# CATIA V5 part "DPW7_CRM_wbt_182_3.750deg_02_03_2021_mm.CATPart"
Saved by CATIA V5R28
Part number: DPW7_CRM_wbt_182_3.750deg_02_03_2021
Bounding box of the stored display mesh (mm): x 2349.5 to 66711.891, y 0 to 29464.422, z 2310.119 to 8715.756
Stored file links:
  Z:\Scratch\04_CAD_Allgemein\Flight2Jig\Output\DPW-7\CATPart\DPW7_CRM_wbt_182_3.750deg_02_03_2021.CATPart
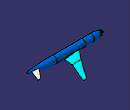
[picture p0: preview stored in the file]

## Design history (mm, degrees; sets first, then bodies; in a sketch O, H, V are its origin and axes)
Set1
  DatumSurface1 "Clean_Wing"
  DatumSurface2 "Fuselage"
  DatumSurface3 "HTP"
  DatumSurface4 "Symmetry"
  DatumSurface5 "Farfield"
Body1 (main body)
